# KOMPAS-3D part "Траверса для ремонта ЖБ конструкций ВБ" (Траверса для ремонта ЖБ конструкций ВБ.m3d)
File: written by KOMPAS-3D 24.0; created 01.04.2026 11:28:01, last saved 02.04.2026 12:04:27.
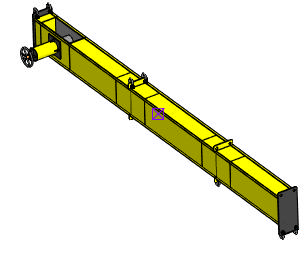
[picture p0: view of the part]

Document properties: Автор: Adm_user; Полное имя файла: C:\Users\PC\Desktop\Для Ильина\СарГЭС\Мостики обслуживания ВБ СарГЭС\Траверса для ремонта ЖБ конструкций ВБ.m3d

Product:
- Body: Тело 1  | qty 1
    Масса: 1617.36582
- Body: Тело 2  | qty 1
    Масса: 171.467837
- Body: Тело 3  | qty 1  | 2 such rows
    Масса: 275.368512
- Body: Тело 4  | qty 1  | 2 such rows
    Масса: 9.4272
- Body: Тело 7  | qty 1
    Масса: 69.654077
- Body: Тело 8  | qty 1
    Масса: 21.9968
- Body: Тело 9  | qty 1
    Масса: 2.820304
- Body: Тело 10  | qty 1
    Масса: 173.787685
- Body: Тело 11  | qty 1  | 2 such rows
    Масса: 17.302695
- Body: Тело 13  | qty 1
    Масса: 0.388872
- Body: Тело 14  | qty 1
    Масса: 16.350733
- Body: Тело 15  | qty 1
    Масса: 5.11346
- Body: Тело 16  | qty 1
    Масса: 0.293079
- Body: Тело 17  | qty 1  | 4 such rows
    Масса: 0.3928
- Body: Тело 21  | qty 1  | 4 such rows
    Масса: 0.1473
- Component [standard]: Подшипник 680206 ГОСТ 24850-81  | qty 1  | additional columns: 680206; source file: ..\..\..\..\..\..\Program Files\ASCON\KOMPAS-3D v24\Libs\PolynomLib\DATA\vault\methods\kompas\3d\Bearings\24850\PLib_Bearing_GOST_24850_1400.a3d
- Body: Тело 25  | qty 1
    Масса: 0.228046
- Body: Тело 26  | qty 1
    Масса: 0.172762
- Body: Тело 27  | qty 1
    Масса: 6.647241
- Body: Тело 28  | qty 1
    Масса: 0.214225
- Component [standard]: Гайка М30x2-6H ГОСТ 15523-70  | qty 1  | Масса: 0.3347; Рассекать на разрезах: no; source file: ..\..\..\..\..\..\Program Files\ASCON\KOMPAS-3D v24\Libs\PolynomLib\DATA\vault\methods\kompas\3d\PLib_Nut_OST92_900.m3d
- Body: Труба / Нестандартная труба / L = 180 мм  | qty 1  | 6 such rows
    Материал: Нестандартная труба (density 7856 kg/m3)
    Масса: 0.442247
    Раздел спецификации: Детали
    Форматы листов документа: БЧ
    Примечание: 0,44 кг
    additional columns: Pipeline; 0.02; 0; 0; 0.005; 0.18; true; 0.04
- Body: Труба / Нестандартная труба / L = 933.2 мм  | qty 1
    Материал: Нестандартная труба (density 7856 kg/m3)
    Масса: 6.978205
    Раздел спецификации: Детали
    Форматы листов документа: БЧ
    Примечание: 6,98 кг
    additional columns: Pipeline; 0.03; 0; 0; 0.005; 0.9332; true; 0.04
- Body: Тело 36  | qty 1
    Масса: 48.222909
- Body: Тело 37  | qty 1
    Масса: 48.222909
- Component [billet]: Скоба г/п 8,5 т  | qty 8  | Масса: 5.231994; source file: ..\..\..\..\Downloads\Другое\Скоба 8,5 т.m3d
- Part/product: Траверса для ремонта ЖБ конструкций ВБ
    Масса: 2841.126319

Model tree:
1. Эскиз:1
2. Элемент выдавливания:1
     Расстояние 1 = 380
3. Элемент выдавливания:3
     Расстояние 1 = 340
4. Эскиз:3  (with: Грань.Элемент выдавливания:3)
5. Элемент выдавливания:4  (with: Вершина.Элемент выдавливания:3)
     Расстояние 1 = 360
6. Эскиз:4  (with: Грань.Элемент выдавливания:4)
7. Элемент выдавливания:5
     Расстояние 1 = 10
8. Эскиз:5  (with: Грань.Элемент выдавливания:1, Вершина.Элемент выдавливания:5, Ребро.Элемент выдавливания:5)
9. Элемент выдавливания:6
     Расстояние 1 = 10
10. Смещенная плоскость:1
     Расстояние = 300
11. Зеркальное отражение:1
12. Экземпляр ( 1 )
13. Экземпляр ( 2 )
14. Тело 3
15. Тело 4
16. Эскиз:6  (with: Грань.Элемент выдавливания:4)
17. Элемент выдавливания:7
     Расстояние 2 = 20
18. Смещенная плоскость:4
     Расстояние = 3390
19. Эскиз:7
20. Элемент выдавливания:8
     Расстояние 1 = 20
21. Эскиз:8
22. Элемент выдавливания:9
     Расстояние 2 = 20
23. Смещенная плоскость:5
     Расстояние = 6425
24. Эскиз:9
25. Элемент выдавливания:10
     Расстояние 2 = 20
26. Эскиз:10  (labels: Грань.Тело 3.Экземпляр ( 2 ))
27. Элемент выдавливания:11  (with: Грань.Элемент выдавливания:9)
     Расстояние 1 = 250
28. Фаска:1  (with: Ребро.Элемент выдавливания:11)
     Угол = 53.1301; Длина 1 = 150; Длина 2 = 200
29. Эскиз:11  (with: Грань.Элемент выдавливания:7)
30. Элемент выдавливания:12
     Расстояние 1 = 10
31. Эскиз:12  (with: Грань.Элемент выдавливания:1)
32. Элемент выдавливания:13  (with: Грань.Элемент выдавливания:1)
     Расстояние 1 = 40; Расстояние 2 = 420; Смещение 2 = 40
33. Фаска:2  (with: Грань.Элемент выдавливания:13)
     Угол = 45; Длина 1 = 10; Длина 2 = 10
34. Эскиз:13  (with: Грань.Элемент выдавливания:1)
35. Элемент выдавливания:14
     Расстояние 1 = 20
36. Зеркальное отражение:2  (with: Экземпляр ( 1 ), Экземпляр ( 2 ))
37. Тело 11
38. Смещенная плоскость:2  (with: Грань.Элемент выдавливания:14)
     Расстояние = 200
39. Эскиз:14
40. Элемент выдавливания:15
     Расстояние 1 = 10
41. Эскиз:15  (labels: Грань.Тело 11.Экземпляр ( 2 ))
42. Элемент выдавливания:16
     Расстояние 1 = 500
43. Эскиз:16  (with: Грань.Элемент выдавливания:16)
44. Элемент выдавливания:17
     Расстояние 1 = 10
45. Эскиз:17  (with: Вершина.Элемент выдавливания:17, Ребро.Элемент выдавливания:17)
46. Эскиз:18  (with: Грань.Элемент выдавливания:17)
47. Элемент выдавливания:18
     Расстояние 1 = 100
48. Эскиз:19  (with: Грань.Элемент выдавливания:17, Ребро.Элемент выдавливания:18)
49. Элемент выдавливания:19  (with: Грань.Элемент выдавливания:18)
     Толщина стенки 1 = 8; Расстояние 1 = 95
50. Фаска:3  (with: Ребро.Элемент выдавливания:19)
     Угол = 45; Длина 1 = 80; Длина 2 = 80
51. Фаска:4  (with: Ребро.Элемент выдавливания:19)
     Угол = 45; Длина 1 = 10; Длина 2 = 10
52. Массив по концентрической сетке:1  (2 pattern instances)
53. Тело 17  (with: Грань.Элемент выдавливания:18)  (2 pattern instances)
     N 1 = 1; Шаг 1 = 10; Шаг 2 = 360; Номер 1 = 1
54. Эскиз:20  (with: Ребро.Элемент выдавливания:16)  (labels: Грань.Тело 11.Экземпляр ( 2 ))
55. Элемент выдавливания:20
     Толщина стенки 1 = 5; Расстояние 1 = 100
56. Фаска:5  (with: Ребро.Элемент выдавливания:20)
     Угол = 60.9454; Длина 1 = 50; Длина 2 = 90
57. Массив по концентрической сетке:2  (2 pattern instances)
58. Тело 21  (with: Грань.Элемент выдавливания:16)  (2 pattern instances)
     N 1 = 1; Шаг 1 = 10; Шаг 2 = 360; Номер 1 = 1
59. Эскиз:22  (with: Грань.Элемент выдавливания:19)
60. Элемент выдавливания:22
     Расстояние 1 = 5
61. Эскиз:21  (with: Грань.Элемент выдавливания:19)
62. Элемент выдавливания:21
     Расстояние 1 = 40
63. Эскиз:23  (with: Грань.Элемент выдавливания:13)
64. Элемент выдавливания:23  (with: Грань.Элемент выдавливания:21)
     Расстояние 1 = -1200
65. Фаска:6  (with: Грань.Элемент выдавливания:23)
     Угол = 45; Длина 1 = 5; Длина 2 = 5
66. Эскиз:24  (with: Грань.Элемент выдавливания:21)
67. Элемент выдавливания:24
     Расстояние 1 = 5
68. Смещенная плоскость:3  (with: Грань.Элемент выдавливания:24)
     Расстояние = 18
69. Эскиз:25  (with: Ребро. Фаска наружная:1)
70. Труба:1  (labels: {F703FF30-5BE6-4673-A7F1-8EDA1BE1E2D1}; SHAPEOBJECT3D_ATTR_BUTT; SHAPEOBJECT3D_ATTR_VALID; SHAPEOBJECT3D_ATTR_BUTT_AREA)
     PIPE_D = 20; PIPE_R = 150
71. Фаска:7  (with: Ребро.Труба:1)
     Угол = 45; Длина 1 = 3; Длина 2 = 3
72. Массив по концентрической сетке:3  (2 pattern instances)
73. Труба Нестандартная труба L = 180 мм  (with: Грань.Элемент выдавливания:23)  (labels: SHAPEOBJECT3D_ATTR_BUTT; SHAPEOBJECT3D_ATTR_VALID; SHAPEOBJECT3D_ATTR_BUTT_AREA; SHAPEOBJECT3D_ATTR_MIN_LEN)  (4 pattern instances)
     N 1 = 1; Шаг 1 = 10; Шаг 2 = 360; Номер 1 = 1
74. Эскиз:26
75. Труба:2  (labels: {F703FF30-5BE6-4673-A7F1-8EDA1BE1E2D1}; SHAPEOBJECT3D_ATTR_VALID; SHAPEOBJECT3D_ATTR_BUTT_AREA; SHAPEOBJECT3D_ATTR_MIN_LEN)
     PIPE_D = 30; PIPE_R = 150
76. Точка в ЦМ:1
     X = -3713.5; Y = 10.0754; Z = -308.344; Координата X = -3713.5; Координата Y = 10.0754; Координата Z = -308.344
77. Фаска:8  (with: Ребро.Элемент выдавливания:12)
     Угол = 45; Длина 1 = 5; Длина 2 = 5
78. Эскиз:27  (with: Ребро.Элемент выдавливания:7, Ребро.Элемент выдавливания:5)
79. Линия-выноска:1  (labels: Палец для установки в траверсу №10; Грань.Тело 11.Экземпляр ( 2 ))
80. Линия-выноска:2  (labels: Грань.Масштабирование : Тело 2.Масштабирование:2)
81. Линия-выноска:3  (labels: для строповки крюком г/п 50,0 т; Грань.Масштабирование : Тело 2.Масштабирование:2)
82. Линия-выноска:4  (labels: Проушины со скобами г/п 16,0 т; для строповки плит 11 т; Грань.Масштабирование : Тело 2.Масштабирование:2)
83. Линия-выноска:5  (labels: Грань.Масштабирование : Тело 2.Масштабирование:2)
84. Точка в ЦМ:2  (with: Грань.Элемент выдавливания:18, Грань.Элемент выдавливания:24, Грань.Элемент выдавливания:23, Грань.Элемент выдавливания:7, Грань.Элемент выдавливания:10, Грань.Элемент выдавливания:8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)  (labels: Грань.Масштабирование : Тело 4.Масштабирование:1; Грань.Масштабирование : Тело 2.Масштабирование:2; SHAPEOBJECT3D_ATTR_BUTT; SHAPEOBJECT3D_ATTR_VALID)
     X = -4111.3; Y = 8.9359; Z = -307.137; Координата X = -4111.3; Координата Y = 8.9359; Координата Z = -307.137; Расстояние = 40; Расстояние = 15; Расстояние = -50; Расстояние = 50

Referenced files in C:\Program Files\ASCON\KOMPAS-3D v24\Libs\EasySteel\: Rolled metal.kle, StandartSolutions.kle, DSTVProperties.lpt
Referenced files in C:\Program Files\ASCON\KOMPAS-3D v24\Templates\: Констр. чертеж А3 гориз. перв. лист.cdt
Referenced files in C:\Program Files\ASCON\KOMPAS-3D v24\Libs\EasySteel\BeltEndings\: 
Referenced files in C:\Program Files\ASCON\KOMPAS-3D v24\Libs\EasySteel\Punctures\: 
Referenced files in C:\Program Files\ASCON\KOMPAS-3D v24\Libs\EasySteel\Insulations\: 
Referenced files in C:\Program Files\ASCON\KOMPAS-3D v24\Libs\Pipeline\: StylesTemplate.a3d, TemplateHPH, InsulationStylesTemplate.a3d, Insulation
Referenced files in C:\Users\PC\Desktop\Для Ильина\СарГЭС\Мостики обслуживания ВБ СарГЭС\: 
Referenced files in C:\Program Files\ASCON\KOMPAS-3D v24\Libs\PolynomLib\DATA\vault\Methods\Kompas\3D\Bearings\24850\: PLib_Bearing_GOST_24850_1400.a3d
Referenced files in C:\Program Files\ASCON\KOMPAS-3D v24\Libs\PolynomLib\DATA\vault\Methods\Kompas\3D\: PLib_Nut_OST92_900.m3d
Referenced files in C:\Users\PC\Downloads\Другое\: Скоба 8,5 т.m3d
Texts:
  Уголок равнополочный по ГОСТ 8509-93 (Спец)
  config2DpacketName
  config2DstdSizeID
  Констр. чертеж А3 гориз. перв. лист.cdt
  Болт ГОСТ 22353-77
  Шайба ГОСТ 22355-77
  Гайка ГОСТ 22354-77
  Нормальная пружинная шайба ГОСТ 6402-70 (исп. 1)
  SeaRox SL 436
  Отводы ГОСТ 17375-2001
  BOSimple***PART:e7b0978b-aa23-2d71-88ea-dfb2c46831d5***SHORTLOC:B6A6_A8780B3C01704A2A[22;35;680206;72]
  BOSimple***PART:12f09448-dd3a-6e44-486b-a13503dfb342***SHORTLOC:Root±30±10±20±©{}110±10±50±170[Нет;Без покрытия;Без указания материала;-;30;2;46]
  Точка начала. Х
  Точка начала. Y
  Точка начала. Z
  bcut1
  hole1
  hcut1
  hole2
  cut1
  Скоба г/п 8,5 т (1)
  Скоба г/п 8,5 т (2)
  Скоба г/п 8,5 т (3)
  Скоба г/п 8,5 т (4)
  Скоба г/п 8,5 т (5)
  Скоба г/п 8,5 т (6)
  Скоба г/п 8,5 т (7)
  Скоба г/п 8,5 т (8)
  Труба / Нестандартная труба / L = %s мм
  Проушины со скобами
  для строповки лесов консольных
  для ремонта пешеходной дорожки ВБ
  Plane. Начало координат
